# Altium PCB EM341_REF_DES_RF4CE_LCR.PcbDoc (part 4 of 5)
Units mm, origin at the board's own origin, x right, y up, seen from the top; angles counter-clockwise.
Board outline 218.38 x 83.13 mm, 2 copper layers (Top Layer, Carbon Ink Layer); 111 components, 91 nets, 369 pads, 80 vias.
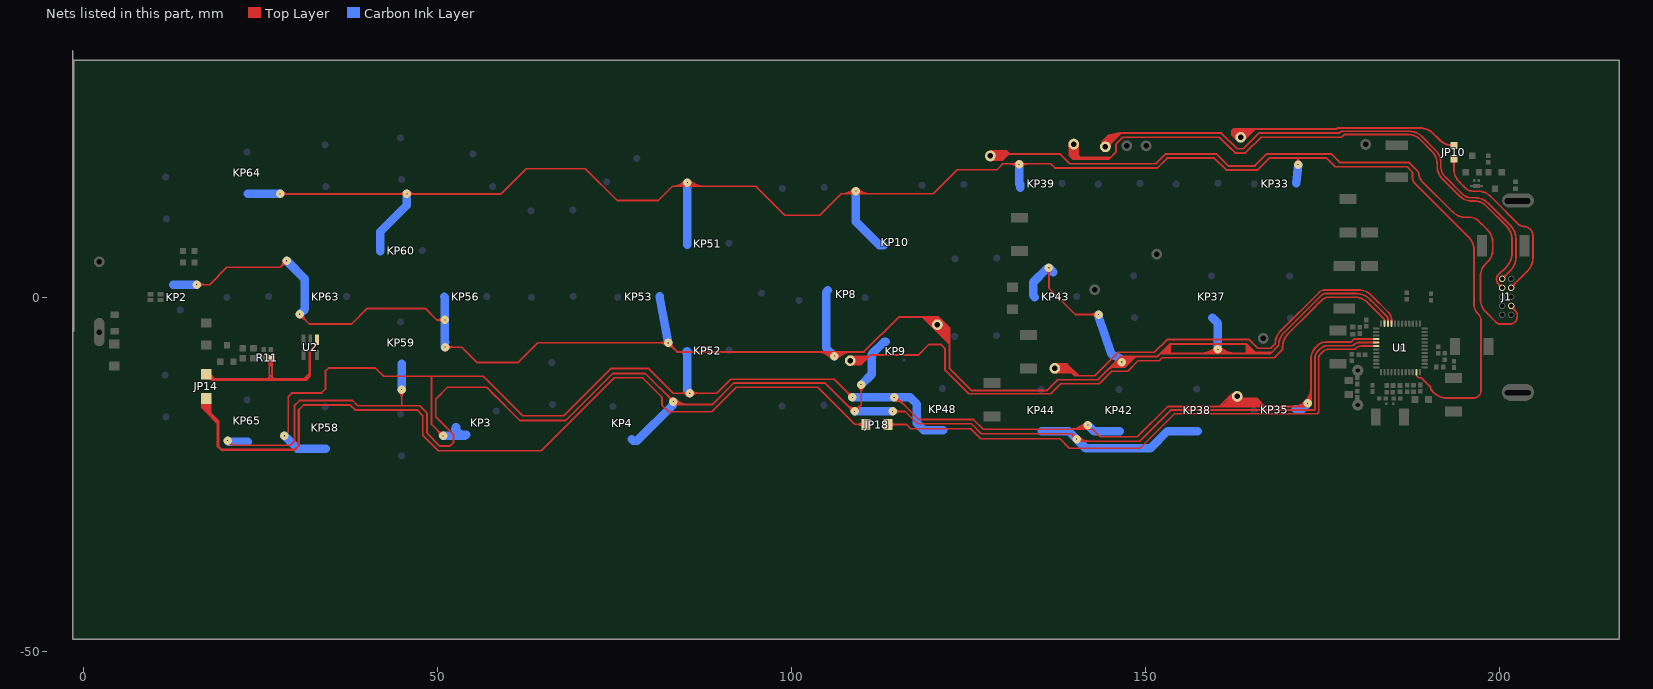
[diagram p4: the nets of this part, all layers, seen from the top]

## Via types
v1: diameter 1.2, hole 0, Top Layer to Carbon Ink Layer, 80 vias

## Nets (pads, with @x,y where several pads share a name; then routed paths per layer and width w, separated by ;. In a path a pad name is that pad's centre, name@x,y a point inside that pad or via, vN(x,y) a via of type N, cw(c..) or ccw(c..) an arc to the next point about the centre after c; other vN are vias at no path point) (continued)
PB6: JP14.2 R11.2 U2.1 | length 64
  Top Layer w0.254: JP14.2@17.31,-10.891 18.149,-11.73 ; JP14.2@17.435,-11.514 cw(c17.59,-12.289) 18.149,-11.73 ; JP14.2@17.447,-11.246 cw(c17.631,-11.722) JP14.2@17.991,-11.361 ; JP14.2@17.86,-10.891 18.699,-11.73 ; JP14.2@17.89,-11.26 18.162,-11.532 18.501,-11.532 ; JP14.2@17.924,-10.955 18.559,-11.59 31.08,-11.59 31.88,-10.79 31.88,-7.66 32.02,-7.52 ; JP14.2@17.933,-11.016 ccw(c18.708,-11.171) 18.149,-11.73 ; JP14.2@17.945,-10.891 ccw(c18.969,-10.891) 18.245,-11.615 ; 24.04,-11.59 25.96,-11.59 26.425,-11.125 ; 25.13,-11.73 31.13,-11.73 32.02,-10.84 32.02,-7.52 ; 25.82,-11.73 20.27,-11.73 18.149,-11.73 ; 26.2,-11.61 26.23,-11.58 26.23,-8.61 R11.2@26.365,-8.475 ; 26.425,-9.664 26.425,-8.475 R11.2@26.365,-8.475 ; 27.01,-11.73 26.62,-11.34 26.62,-8.825 26.365,-8.57 R11.2@26.365,-8.475 ; 30.44,-11.73 31.42,-11.73 32.02,-11.13 32.02,-10.6 ; U2.1@32.96,-5.92 32.96,-6.031 U2.1@32.954,-6.037 32.954,-6.586 32.02,-7.52 ; R11.2@26.285,-8.74 cw(c25.947,-9.078) 26.425,-9.078 ; R11.2@26.285,-8.74 cw(c25.947,-9.078) 26.425,-9.078 ; R11.2@26.285,-8.74 cw(c25.947,-9.078) 26.425,-9.078 ; R11.2@26.285,-8.74 cw(c25.947,-9.078) 26.425,-9.078 ; R11.2@26.285,-8.74 cw(c25.947,-9.078) 26.425,-9.078 ; R11.2@26.285,-8.74 cw(c25.947,-9.078) 26.425,-9.078 ; R11.2@26.285,-8.74 cw(c25.947,-9.078) 26.425,-9.078 ; R11.2@26.285,-8.74 cw(c25.947,-9.078) 26.425,-9.078 ; 26.425,-9.078 cw(c26.903,-9.078) R11.2@26.565,-8.74 ; 26.425,-9.078 cw(c26.903,-9.078) R11.2@26.565,-8.74 ; 26.425,-9.078 cw(c26.903,-9.078) R11.2@26.565,-8.74 ; 26.425,-9.078 cw(c26.903,-9.078) R11.2@26.565,-8.74 ; 26.425,-9.078 cw(c26.903,-9.078) R11.2@26.565,-8.74 ; 26.425,-9.078 cw(c26.903,-9.078) R11.2@26.565,-8.74 ; 26.425,-9.078 cw(c26.903,-9.078) R11.2@26.565,-8.74 ; 26.425,-9.078 cw(c26.903,-9.078) R11.2@26.565,-8.74 ; 32.631,-6.909 ccw(c32.21,-6.487) 32.806,-6.487 cw(c32.21,-6.487) 32.631,-6.909
PB6_1: JP14.1 JP18.2 | length 184.2
  Top Layer w0.254: 16.68,-15.453 cw(c17.439,-15.453) JP14.1@17.353,-14.699 ; 16.68,-15.168 cw(c17.407,-15.168) JP14.1@17.324,-14.446 ; 16.68,-15.11 17.493,-16.043 ; JP14.1@16.68,-14.884 cw(c17.374,-14.884) JP14.1@17.296,-14.194 ; JP14.1@16.68,-14.55 16.68,-15.59 17.429,-16.339 ; 16.92,-15.648 cw(c17.658,-15.648) JP14.1@17.471,-14.934 ; 16.92,-15.319 cw(c17.572,-15.319) JP14.1@17.407,-14.689 ; JP14.1@16.92,-14.99 cw(c17.486,-14.99) JP14.1@17.342,-14.443 ; JP14.1@16.92,-14.92 16.92,-15.59 17.16,-15.83 ; JP14.1@16.934,-14.831 cw(c16.127,-15.927) 17.488,-15.927 ; JP14.1@16.978,-14.861 cw(c16.149,-16.211) 17.733,-16.211 ; JP14.1@17.003,-14.876 cw(c16.125,-16.465) 17.94,-16.465 ; JP14.1@17.041,-14.589 cw(c16.39,-15.24) 17.31,-15.24 cw(c18.23,-15.24) JP14.1@17.579,-14.589 ; JP14.1@17.084,-14.627 cw(c16.496,-15.425) 17.488,-15.425 ; JP14.1@17.111,-14.645 cw(c16.428,-15.757) 17.733,-15.757 ; JP14.1@17.126,-14.653 cw(c16.363,-16.034) 17.94,-16.034 ; 17.16,-15.997 cw(c18.708,-15.997) JP14.1@17.717,-14.808 ; 17.16,-15.99 JP14.1@17.16,-14.57 ; 17.16,-15.491 ccw(c16.139,-15.491) 16.861,-14.769 cw(c15.777,-15.853) 17.31,-15.853 cw(c18.843,-15.853) 17.759,-14.769 ccw(c18.414,-15.424) 17.488,-15.424 ; 17.16,-15.454 cw(c18.256,-15.454) JP14.1@17.554,-14.613 ; JP14.1@17.244,-14.428 cw(c16.707,-15.303) 17.733,-15.303 ; JP14.1@17.249,-14.431 cw(c16.601,-15.603) 17.94,-15.603 ; JP14.1@17.31,-14.32 17.31,-16.22 18.9,-17.81 18.9,-21.04 19.47,-21.61 29.8,-21.61 30.42,-20.99 30.42,-15.89 ; JP14.1@17.371,-14.209 cw(c16.839,-15.173) 17.94,-15.173 ; 17.46,-16.17 19.04,-17.75 ; 17.488,-15.918 JP14.1@17.488,-14.802 ; JP14.1@17.733,-14.843 17.493,-16.043 ; JP14.1@17.94,-14.74 17.94,-16.37 19.04,-17.47 19.04,-21.07 19.58,-21.61 ; 18.92,-17.47 17.493,-16.043 ; 19.5,-21.5 29.82,-21.5 30.42,-20.9 ; 30.31,-21.01 30.31,-16 31.05,-15.26 37.66,-15.26 38.34,-15.94 47.09,-15.94 47.89,-16.74 47.89,-19.5 50.1,-21.71 64.62,-21.71 74.92,-11.41 78.93,-11.41 81.68,-14.16 81.68,-15.25 82.64,-16.21 88.7,-16.21 92.17,-12.74 103.64,-12.74 ; 103.66,-12.74 108.87,-17.95 JP18.2@110.428,-17.95 ; 109.117,-17.95 cw(c109.117,-19.383) JP18.2@110.13,-18.37 ; 109.358,-17.95 ccw(c109.358,-16.858) JP18.2@110.13,-17.63 ; 109.73,-17.95 cw(c109.73,-18.77) JP18.2@110.31,-18.19
PB6_2: JP18.1 U1.42 | length 82.9
  Top Layer w0.254: JP18.1@113.6,-18 116.22,-18 116.82,-18.6 125.28,-18.6 126.7,-20.02 137.88,-20.02 139.21,-21.35 149.18,-21.35 154.054,-16.476 174.103,-16.476 ccw(c174.103,-16.108) 174.364,-16.369 ccw(c174.239,-16.244) 174.416,-16.244 174.416,-8.618 cw(c175.208,-8.618) 174.647,-8.057 174.982,-7.723 cw(c175.8,-8.541) 175.8,-7.384 179.363,-7.384 ccw(c179.363,-7.076) 179.581,-7.294 179.698,-7.177 ; JP18.1@113.97,-18.37 cw(c114.863,-19.263) 114.863,-18 cw(c114.863,-16.737) JP18.1@113.97,-17.63 ; 179.653,-7.22 cw(c180.365,-7.932) 179.698,-7.177 ; U1.42@182.528,-6.925 180.365,-6.925 ccw(c180.365,-7.932) 179.698,-7.177
PB7: KP4.2 KP9.1 KP38.2 KP44.1 KP59.2 KP65.2 U1.41 | length 305.2
  Top Layer w0.254: v1(20.33,-20.28) 20.98,-20.93 ; 44.92,-15.33 v1(44.92,-13.07) ; 57.68,-13.51 61.6,-17.43 68.09,-17.43 74.73,-10.79 79.32,-10.79 v1@83.261,-14.731 ; 58.228,-14.058 56.92,-12.75 51.39,-12.75 49.72,-14.42 49.72,-16.9 52.25,-19.43 52.25,-20.5 51.7,-21.05 50.32,-21.05 48.51,-19.24 48.51,-16.39 47.48,-15.36 38.72,-15.36 37.97,-14.61 30.51,-14.61 29.77,-15.35 29.77,-20.36 29.2,-20.93 20.98,-20.93 ; v1@83.72,-15.19 88.78,-15.19 91.85,-12.12 104.66,-12.12 108.68,-16.14 v1(108.89,-16.14) 109.83,-15.2 109.83,-12.33 v1(109.79,-12.37) ; v1(114.25,-16.16) 116.02,-16.16 117.76,-17.9 125.38,-17.9 126.77,-19.29 139.55,-19.29 140.61,-20.35 149.14,-20.35 153.522,-15.968 173.67,-15.968 ccw(c173.67,-15.735) 173.835,-15.9 ccw(c173.687,-15.752) 173.896,-15.752 173.896,-8.553 cw(c175.061,-8.553) 174.237,-7.729 174.717,-7.249 cw(c175.618,-8.151) 175.618,-6.876 178.983,-6.876 ccw(c178.983,-6.215) 179.45,-6.683 cw(c180.072,-7.304) 180.072,-6.425 U1.41@182.528,-6.425 ; 20.98,-20.93 cw(c21.444,-20.466) 20.797,-20.358 ccw(c21.444,-20.466) 20.98,-20.93 ; 20.98,-20.93 ccw(c20.516,-21.394) 20.408,-20.747 cw(c20.516,-21.394) 20.98,-20.93 ; 44.92,-14.212 cw(c46.062,-14.212) 45.254,-13.404 ccw(c46.062,-14.212) 44.92,-14.212 ; 44.92,-14.212 ccw(c43.778,-14.212) 44.586,-13.404 cw(c43.778,-14.212) 44.92,-14.212 ; 82.493,-13.963 cw(c81.685,-14.77) 82.827,-14.77 ccw(c81.685,-14.77) 82.493,-13.963 ; 82.493,-13.963 ccw(c83.3,-13.155) 83.3,-14.297 cw(c83.3,-13.155) 82.493,-13.963 ; v1@108.89,-15.667 cw(c108.89,-14.018) 107.724,-15.184 ccw(c108.89,-14.018) v1@108.89,-15.667 ; v1@108.89,-15.667 ccw(c108.89,-14.525) 109.697,-15.333 ; v1@108.89,-15.667 ccw(c108.89,-14.525) 109.697,-15.333 ; 109.697,-15.333 ccw(c110.505,-16.14) 109.363,-16.14 cw(c110.505,-16.14) 109.697,-15.333 ; 115.392,-16.16 cw(c115.392,-15.018) 114.584,-15.826 ccw(c115.392,-15.018) 115.392,-16.16 ; 115.392,-16.16 ccw(c115.392,-17.302) 114.584,-16.494 cw(c115.392,-17.302) 115.392,-16.16 ; v1@83.275,-14.795 ccw(c84.229,-13.841) 84.229,-15.19 cw(c84.229,-13.841) v1@83.275,-14.795 ; v1@83.455,-14.615 ccw(c84.843,-13.227) 84.843,-15.19 cw(c84.843,-13.227) v1@83.455,-14.615 ; v1@83.634,-14.436 ccw(c85.456,-12.614) 85.456,-15.19 cw(c85.456,-12.614) v1@83.634,-14.436 ; 108.158,-15.618 ccw(c108.89,-14.885) 108.89,-15.921 cw(c108.89,-14.885) 108.158,-15.618 ; 108.231,-15.691 cw(c107.782,-16.14) 108.417,-16.14 ccw(c107.782,-16.14) 108.231,-15.691 ; v1@109.456,-12.704 cw(c108.552,-13.608) 109.83,-13.608 ccw(c108.552,-13.608) v1@109.456,-12.704 ; v1@109.635,-12.525 cw(c109.165,-12.995) 109.83,-12.995 ccw(c109.165,-12.995) v1@109.635,-12.525 ; 109.83,-13.415 cw(c110.835,-13.415) 110.124,-12.704 ccw(c110.835,-13.415) 109.83,-13.415 ; 139.505,-19.245 cw(c138.869,-19.881) 139.761,-19.998 ccw(c138.869,-19.881) 139.505,-19.245 ; 139.576,-19.316 ccw(c140.23,-18.662) 140.23,-19.587 cw(c140.23,-18.662) 139.576,-19.316 ; v1@140.205,-20.085 ccw(c140.846,-19.444) 140.846,-20.35 cw(c140.846,-19.444) v1@140.205,-20.085 ; v1@140.385,-19.905 ccw(c141.459,-18.831) 141.459,-20.35 cw(c141.459,-18.831) v1@140.385,-19.905 ; v1@140.564,-19.726 ccw(c142.072,-18.218) 142.072,-20.35 cw(c142.072,-18.218) v1@140.564,-19.726
  Carbon Ink Layer w1.2: v1(20.33,-20.28) 20.467,-20.417 KP65.2@23.21,-20.417 ; v1@44.91,-13.05 KP59.2@44.91,-9.44 ; KP4.2@77.434,-20.114 77.59,-20.27 78.18,-20.27 83.3,-15.15 v1(83.3,-14.77) ; v1@108.89,-16.15 v1@114.25,-16.14 ; v1(109.79,-12.37) 109.79,-12.41 111.3,-10.9 111.3,-8.06 113.08,-6.28 KP9.1@113.309,-6.28 ; KP44.1@135.33,-18.966 139.136,-18.966 141.52,-21.35 150.65,-21.35 153.083,-18.917 KP38.2@157.31,-18.917 ; v1(83.3,-14.77) cw(c82.383,-14.77) 83.031,-15.419 ccw(c82.383,-14.77) v1(83.3,-14.77)
  other v1: 140.23,-20.06
PC0: 
PC0_1: 
PC0_2: KP3.1 KP35.2 KP42.1 KP48.2 KP52.2 KP58.2 pad.8 U1.40 | length 322.5
  Top Layer w0.254: v1(28.36,-19.58) 28.9,-19.04 28.9,-14.08 29.45,-13.53 33.6,-13.53 34.14,-12.99 34.14,-10.48 34.6,-10.02 41.2,-10.02 42.37,-11.19 56.44,-11.19 62.02,-16.77 67.8,-16.77 74.47,-10.1 79.81,-10.1 83.29,-13.58 89.41,-13.58 91.39,-11.6 106,-11.6 v1(108.57,-14.17) ; 49.13,-11.23 49.13,-17.99 v1(50.76,-19.62) ; v1@114.84,-14.55 114.85,-14.18 117.96,-17.29 125.66,-17.29 127.03,-18.66 142.49,-18.66 143.57,-19.74 148.81,-19.74 153.09,-15.46 172.997,-15.46 ccw(c172.997,-15.134) 173.227,-15.365 ccw(c172.986,-15.124) 173.327,-15.124 173.327,-8.787 cw(c175.867,-8.787) 174.071,-6.991 174.196,-6.866 cw(c175.399,-8.069) 175.399,-6.368 178.853,-6.368 ccw(c178.853,-6.05) 179.077,-6.275 179.442,-5.91 182.513,-5.91 U1.40@182.528,-5.925 ; 160.399,-15.46 162.148,-13.712 ; 160.606,-15.254 160.936,-15.254 pad.8@162.208,-13.982 ; 161.06,-15.46 pad.8@162.428,-14.092 ; 161.412,-15.368 pad.8@162.628,-14.152 ; 161.672,-15.358 pad.8@162.888,-14.142 ; 161.832,-15.398 pad.8@163.048,-14.182 ; 162.032,-15.408 pad.8@163.248,-14.192 ; 162.27,-15.361 pad.8@162.27,-13.64 ; pad.8@162.451,-14.279 cw(c161.367,-15.363) 162.9,-15.363 cw(c164.433,-15.363) pad.8@163.349,-14.279 ; 162.47,-15.45 pad.8@162.47,-13.73 ; 162.59,-15.45 pad.8@162.59,-13.73 ; pad.8@162.631,-14.099 cw(c161.98,-14.75) 162.9,-14.75 cw(c163.82,-14.75) pad.8@163.169,-14.099 ; 162.81,-15.46 pad.8@162.81,-13.74 ; 162.9,-15.46 pad.8@162.9,-13.74 ; 163.1,-15.46 pad.8@163.1,-13.74 ; 163.24,-15.46 pad.8@163.24,-13.74 ; 163.349,-15.38 pad.8@163.349,-13.659 ; 163.55,-15.44 pad.8@163.55,-13.72 ; 163.59,-14.76 165.65,-14.76 166.23,-15.34 ; 163.63,-14.95 165.66,-14.95 166.06,-15.35 ; 163.64,-14.52 165.63,-14.52 166.46,-15.35 ; 163.689,-14.3 165.66,-14.3 166.67,-15.31 ; 163.709,-15.2 165.76,-15.2 165.9,-15.34 ; 170.679,-15.46 ccw(c170.679,-12.849) 172.526,-14.696 ccw(c170.589,-12.759) 173.327,-12.759 ; 171.292,-15.46 ccw(c171.292,-13.462) 172.705,-14.875 ccw(c171.203,-13.373) 173.327,-13.373 ; 171.905,-15.46 ccw(c171.905,-14.075) 172.885,-15.055 ccw(c171.816,-13.986) 173.327,-13.986 ; v1@173.064,-15.234 ccw(c172.429,-14.599) 173.327,-14.599 ; v1@173.18,-15.28 v1@173.24,-15.22 ; 49.953,-18.813 cw(c49.145,-19.62) 50.287,-19.62 ccw(c49.145,-19.62) 49.953,-18.813 ; 49.953,-18.813 ccw(c50.76,-18.005) 50.76,-19.147 cw(c50.76,-18.005) 49.953,-18.813 ; 84.458,-13.58 cw(c84.458,-14.722) 85.266,-13.914 ccw(c84.458,-14.722) 84.458,-13.58 ; 84.458,-13.58 ccw(c84.458,-12.438) 85.266,-13.246 cw(c84.458,-12.438) 84.458,-13.58 ; 86.742,-13.58 cw(c86.742,-12.438) 85.934,-13.246 ccw(c86.742,-12.438) 86.742,-13.58 ; 86.742,-13.58 ccw(c86.742,-14.722) 85.934,-13.914 cw(c86.742,-14.722) 86.742,-13.58 ; 107.763,-13.363 cw(c106.955,-14.17) 108.097,-14.17 ccw(c106.955,-14.17) 107.763,-13.363 ; 107.763,-13.363 ccw(c108.57,-12.555) 108.57,-13.697 cw(c108.57,-12.555) 107.763,-13.363 ; v1@114.47,-14.643 cw(c114.47,-16.678) 115.909,-15.239 ccw(c114.47,-16.678) v1@114.47,-14.643 ; v1@114.47,-14.389 cw(c114.47,-15.811) 115.475,-14.805 ccw(c114.47,-15.811) v1@114.47,-14.389 ; v1@114.47,-14.135 cw(c114.47,-14.944) 115.042,-14.372 ccw(c114.47,-14.944) v1@114.47,-14.135 ; 139.268,-18.66 ccw(c139.268,-15.538) 141.476,-17.746 cw(c139.268,-15.538) 139.268,-18.66 ; 139.881,-18.66 ccw(c139.881,-16.151) 141.655,-17.925 cw(c139.881,-16.151) 139.881,-18.66 ; 140.494,-18.66 ccw(c140.494,-16.764) 141.835,-18.105 cw(c140.494,-16.764) 140.494,-18.66 ; 141.107,-18.66 ccw(c141.107,-17.377) 142.014,-18.284 cw(c141.107,-17.377) 141.107,-18.66
  Carbon Ink Layer w1.2: v1(28.36,-19.58) 30.187,-21.407 KP58.2@34.21,-21.407 ; v1@50.77,-19.61 51.05,-19.61 51.06,-19.62 53.83,-19.62 KP3.1@53.93,-19.52 ; 52.48,-18.69 53.227,-19.437 KP3.1@54.04,-19.437 ; 52.56,-18.38 52.61,-18.38 ; KP52.2@85.08,-7.773 KP52.2@85.223,-7.63 85.223,-13.203 v1(85.6,-13.58) ; v1(108.57,-14.17) v1@114.46,-14.17 ; v1(114.47,-14.17) 116.73,-14.17 117.68,-15.12 117.68,-17.83 118.667,-18.817 KP48.2@121.4,-18.817 ; v1(141.81,-18.08) 142.686,-18.956 KP42.1@146.33,-18.956 ; KP35.2@171.187,-15.86 172.03,-15.86 v1(172.86,-15.03) ; v1(85.6,-13.58) cw(c86.51,-12.67) 85.223,-12.67 ccw(c86.51,-12.67) v1(85.6,-13.58)
PC0_3: JP10.1 pad.0@163.4,22.55 | length 61.3
  Top Layer w0.254: 162.174,23.126 pad.0@162.945,22.355 ; 162.244,23.276 pad.0@163.015,22.505 ; 162.244,23.416 pad.0@163.015,22.645 ; 162.324,23.526 pad.0@163.095,22.755 ; 162.504,23.566 pad.0@163.275,22.795 ; 162.61,22.81 cw(c163.19,22.72) pad.0@163.28,23.3 ; 162.644,23.606 pad.0@163.415,22.835 ; pad.0@162.82,22.22 162.15,22.89 162.15,23.48 162.41,23.74 176.95,23.74 177.075,23.865 188.74,23.865 ; 162.834,23.606 pad.0@163.605,22.835 ; 162.994,23.636 pad.0@163.765,22.865 ; 163.102,23.395 164.192,23.395 ; 163.113,23.267 cw(c163.459,22.793) 163.933,23.14 ; 163.114,23.646 pad.0@163.885,22.875 ; 163.177,23.54 164.267,23.54 ; 163.274,23.656 pad.0@164.045,22.885 ; pad.0@163.4,22.931 ccw(c163.4,23.73) 163.965,23.165 ; pad.0@163.4,23.185 ccw(c163.4,24.597) 164.399,23.599 ; pad.0@163.48,22.68 164.54,23.74 ; 163.66,23.28 cw(c163.57,22.7) pad.0@164.15,22.61 ; pad.0@163.71,22.29 164,22.29 165.395,23.685 ; pad.0@163.781,22.55 cw(c164.822,22.55) 164.086,23.286 ; pad.0@164.035,22.55 cw(c165.689,22.55) 164.519,23.719 ; pad.0@164.054,22.904 164.825,23.675 ; 164.234,22.914 165.005,23.685 ; 164.254,22.784 165.025,23.555
  Top Layer w0.292: 188.74,23.865 cw(c188.74,21.325) 190.536,23.121 191.484,22.174 ccw(c193.28,23.97) 193.28,21.43 JP10.1@193.514,21.43 ; JP10.1@193.195,21.775 cw(c193.195,21.34) 193.503,21.648 cw(c193.394,21.539) 193.547,21.539 JP10.1@193.547,21.32
PC0_4: J1.3 JP10.2 | length 31.9
  Top Layer w0.254: JP10.2@193.514,19.53 193.514,18.057 ccw(c196.054,18.057) 194.258,16.261 194.795,15.724 194.799,15.724 195.127,15.396 ccw(c196.218,16.488) 196.218,14.944 196.911,14.944 cw(c196.911,12.404) 198.518,14.371 cw(c196.911,12.404) 198.707,14.2 198.99,13.918 ; 198.986,13.914 202.606,10.294 ccw(c203.382,11.071) 203.382,9.972 cw(c203.382,8.771) 204.232,9.621 204.321,9.532 cw(c203.501,8.712) 204.66,8.712 204.66,5.5 cw(c202.12,5.5) 203.916,3.704 J1.3@201.595,1.382 ; 193.514,18.63 cw(c194.415,18.63) 193.778,19.266 ccw(c194.415,18.63) 193.514,18.63 ; 193.514,18.63 ccw(c192.614,18.63) 193.25,19.266 cw(c192.614,18.63) 193.514,18.63 ; J1.3@201.585,1.618 ccw(c201.585,2.211) 202.004,1.792 ; J1.3@201.585,1.618 ccw(c201.585,2.211) 202.004,1.792 ; J1.3@201.585,1.618 ccw(c201.585,2.211) 202.004,1.792 ; J1.3@201.908,1.295 cw(c202.875,1.295) 202.191,1.979 ; J1.3@201.908,1.295 cw(c202.875,1.295) 202.191,1.979 ; J1.3@201.908,1.295 cw(c202.875,1.295) 202.191,1.979
PC0_5: 
PC2: pad.1@137.15,-10.07 U1.33 | length 82
  Top Layer w0.254: pad.1@136.59,-10.3 139.57,-10.3 ; pad.1@136.64,-9.73 138.837,-9.73 ; pad.1@136.66,-10.07 138.12,-10.07 ; pad.1@136.73,-10.15 138.19,-10.15 ; pad.1@136.74,-10.5 139.67,-10.5 ; pad.1@136.74,-9.96 139.22,-9.96 ; pad.1@136.85,-9.53 137.98,-9.53 ; pad.1@136.96,-10.67 139.84,-10.67 140.27,-11.1 ; pad.1@136.99,-9.45 138.87,-9.45 140.52,-11.1 ; pad.1@137.44,-9.55 138.9,-9.55 ; pad.1@137.64,-9.84 139.1,-9.84 ; 137.92,-10.1 139.38,-10.1 ; 138.855,-10.01 139.945,-11.1 142.78,-11.1 146.08,-7.8 151.22,-7.8 153.01,-6.01 164.59,-6.01 165.81,-7.23 167.651,-7.23 168.265,-6.616 cw(c170.805,-6.616) 169.009,-4.82 174.537,0.708 cw(c175.268,-0.023) 175.268,1.01 ; 138.967,-9.57 138.978,-9.558 ; 175.291,0.999 180.038,0.999 cw(c180.038,-1.541) 181.834,0.255 184.266,-2.176 ; 184.245,-2.152 cw(c183.138,-3.259) 184.703,-3.259 U1.33@184.703,-3.75
PC2_1: 
PC2_2: 
PC2_3: J1.2 pad.2@144.3,21.22 | length 135.8
  Top Layer w0.254: pad.2@143.9,21.28 143.9,22.02 144.68,22.8 146.27,23.16 ; pad.2@144.003,21.857 cw(c144.349,21.383) pad.2@144.823,21.73 ; pad.2@144.16,21.26 144.16,22.06 144.71,22.61 145.48,22.61 ; pad.2@144.19,21.08 146.27,23.16 ; pad.2@144.3,21.4 145.7,22.8 ; pad.2@144.32,21.69 144.32,21.92 144.96,22.56 ; pad.2@144.6,21.27 146.49,23.16 ; 145.91,22.95 144.96,22.61 144.96,22.56 ; 188.955,22.684 190.904,20.736 cw(c189.108,18.939) 191.648,18.939 191.648,18.555 ccw(c193.983,18.555) 192.332,16.903 194.655,14.58 ccw(c196.026,15.951) 196.026,14.012 196.568,14.012 cw(c196.568,11.608) 198.268,13.308 201.521,10.054 cw(c199.725,8.258) 202.265,8.258 202.265,5.567 cw(c199.725,5.567) 201.521,3.771 J1.2@200.315,2.565 ; 188.962,22.691 ccw(c187.245,20.974) 187.245,23.402 177.582,23.402 177.34,23.16 165.97,23.16 163.74,20.93 162.91,20.93 160.68,23.16 146.27,23.16 ; pad.2@144.3,21.601 ccw(c144.3,23.124) 145.377,22.047 cw(c144.3,23.124) pad.2@144.3,21.601 ; pad.2@144.3,21.601 ccw(c144.3,22.593) 145.002,21.892 cw(c144.3,22.593) pad.2@144.3,21.601 ; pad.2@144.3,21.855 ccw(c144.3,22.326) 144.633,21.993 cw(c144.3,22.326) pad.2@144.3,21.855 ; pad.2@144.3,21.855 ccw(c144.3,23.992) 145.811,22.481 cw(c144.3,23.992) pad.2@144.3,21.855 ; pad.2@144.3,21.855 ccw(c144.3,23.46) 145.435,22.325 cw(c144.3,23.46) pad.2@144.3,21.855 ; pad.2@144.3,21.855 ccw(c144.3,22.881) 145.026,22.156 cw(c144.3,22.881) pad.2@144.3,21.855 ; pad.2@144.3,21.855 ccw(c144.3,22.953) 145.077,22.177 cw(c144.3,22.953) pad.2@144.3,21.855 ; pad.2@144.681,21.22 cw(c145.528,21.22) 144.929,21.819 ccw(c145.528,21.22) pad.2@144.681,21.22 ; pad.2@144.681,21.22 cw(c146.035,21.22) 145.078,22.178 ccw(c146.035,21.22) pad.2@144.681,21.22 ; pad.2@144.935,21.22 cw(c145.864,21.22) 145.207,21.877 ccw(c145.864,21.22) pad.2@144.935,21.22 ; pad.2@144.935,21.22 cw(c146.396,21.22) 145.363,22.253 ccw(c146.396,21.22) pad.2@144.935,21.22 ; pad.2@144.935,21.22 cw(c146.903,21.22) 145.511,22.611 ccw(c146.903,21.22) pad.2@144.935,21.22 ; 144.96,22.56 ccw(c145.539,21.981) 144.841,21.552 cw(c145.539,21.981) 144.96,22.56 ; 145.15,22.51 ccw(c145.891,21.769) 144.9,21.427 cw(c145.891,21.769) 145.15,22.51 ; 145.15,22.51 144.49,21.85 144.49,21.62 145.48,22.61 ; 145.48,22.61 ccw(c146.798,21.292) 144.935,21.238 cw(c146.798,21.292) 145.48,22.61 ; J1.2@200.315,2.888 ccw(c200.315,3.668) 200.866,3.116 ; J1.2@200.315,2.888 ccw(c200.315,3.668) 200.866,3.116 ; J1.2@200.315,2.888 ccw(c200.315,3.668) 200.866,3.116 ; J1.2@200.638,2.565 cw(c201.418,2.565) 200.866,3.116 ; J1.2@200.638,2.565 cw(c201.418,2.565) 200.866,3.116 ; J1.2@200.638,2.565 cw(c201.418,2.565) 200.866,3.116 ; pad.2@144.408,21.286 cw(c144.975,21.634) 144.505,22.105 ccw(c144.975,21.634) pad.2@144.408,21.286 ; pad.2@144.42,21.261 cw(c145.037,21.474) 144.575,21.935 ccw(c145.037,21.474) pad.2@144.42,21.261 ; pad.2@144.625,21.419 cw(c145.257,21.808) 144.732,22.332 ccw(c145.257,21.808) pad.2@144.625,21.419 ; pad.2@144.66,21.344 cw(c145.464,21.622) 144.863,22.223 ccw(c145.464,21.622) pad.2@144.66,21.344 ; pad.2@144.681,21.231 cw(c145.988,21.269) 145.063,22.193 ccw(c145.988,21.269) pad.2@144.681,21.231
PC3: KP2.2 KP8.1 KP37.2 KP43.2 KP53.1 KP56.2 KP63.2 pad.0@120.57,-3.91 U1.34 | length 642.3
  Top Layer w0.254: v1@15.98,1.75 17.79,1.75 20.24,4.2 27.74,4.2 v1@28.695,5.155 ; v1@16.294,1.436 cw(c17.054,0.676) 17.054,1.75 ; v1@16.294,2.104 ccw(c17.15,2.96) 17.15,1.75 ; v1@28.197,5.13 cw(c27.055,5.13) 27.863,4.323 cw(c28.67,3.515) v1@28.67,4.657 ; v1(30.51,-2.43) 31.88,-3.8 37.88,-3.8 40.07,-1.61 48.25,-1.61 49.879,-3.239 v1(51.029,-3.239) ; v1@51,-7.08 53.4,-7.08 55.58,-9.26 61.3,-9.26 63.48,-7.08 ; v1@51.374,-7.414 cw(c52.182,-8.222) 52.182,-7.08 cw(c52.182,-5.938) v1@51.374,-6.746 ; 62.419,-8.141 64.12,-6.44 82.5,-6.44 83.81,-7.75 110.19,-7.75 115.11,-2.83 120.73,-2.83 122.26,-4.36 122.26,-10.05 125.418,-13.208 136.032,-13.208 137.56,-11.68 143.19,-11.68 146.46,-8.41 151.63,-8.41 153.43,-6.61 ; 81.322,-6.44 cw(c81.322,-7.718) v1@82.226,-6.814 ; 81.515,-6.44 ccw(c81.515,-5.435) v1@82.226,-6.146 ; 81.935,-6.44 cw(c81.935,-7.105) v1@82.405,-6.635 ; v1@82.56,-6.953 cw(c82.56,-8.047) 83.333,-7.273 ; v1@83.033,-6.48 ccw(c84.223,-6.48) 83.382,-7.322 ; 104.81,-7.75 104.83,-7.77 v1(106.02,-8.35) ; 118.47,-2.83 122.26,-6.62 ; 118.76,-2.83 122.26,-6.33 ; 119.43,-3.01 121.99,-5.57 ; pad.0@119.937,-3.859 119.988,-3.228 122.26,-5.5 ; 120.1,-3.01 122.1,-5.01 ; 120.49,-2.83 122.1,-4.44 122.1,-5.96 119.15,-3.01 120.44,-3.01 122.05,-4.62 ; pad.0@120.613,-4.03 cw(c121.16,-5.564) 122.312,-4.412 ; v1@135.976,3.806 cw(c135.168,2.998) 136.31,2.998 cw(c137.452,2.998) v1@136.644,3.806 ; v1@136.023,3.77 cw(c135.521,3.148) 136.32,3.148 cw(c137.119,3.148) v1@136.617,3.77 ; v1(136.31,4.14) 136.31,1.28 140.07,-2.48 v1(143.33,-2.48) ; v1@142.922,-2.777 ccw(c142.3,-3.279) 142.3,-2.48 ccw(c142.3,-1.681) v1@142.922,-2.183 ; v1@142.996,-2.814 ccw(c142.188,-3.622) 142.188,-2.48 ccw(c142.188,-1.338) v1@142.996,-2.146 ; 147.31,-8.86 146.8,-9.37 145.96,-9.37 ; 147.87,-8.52 147.87,-8.61 ; 148.5,-8.41 147,-9.91 144.96,-9.91 ; 152.07,-7.97 167.63,-7.97 168.772,-6.827 cw(c171.312,-6.827) 169.516,-5.031 173.471,-1.077 ; 152.37,-7.84 152.42,-7.84 153.08,-7.18 153.08,-7.75 152.72,-7.75 152.65,-7.82 152.77,-7.82 153.08,-7.51 ; 153.217,-7.753 153.217,-6.823 ; 153.43,-7.9 153.43,-6.61 ; v1(160.19,-7.4) 160.19,-6.62 ; 164.38,-6.92 165.27,-7.81 164.37,-7.81 164.22,-7.96 164.22,-6.61 ; 164.4,-6.94 164.4,-7.62 164.424,-7.596 165.056,-7.596 ; 164.69,-7.23 164.53,-7.23 164.57,-7.27 164.57,-7.596 164.71,-7.456 ; 167.81,-7.79 165.4,-7.79 164.22,-6.61 ; 173.47,-1.085 174.806,0.251 cw(c175.386,-0.33) 175.386,0.491 179.784,0.491 cw(c179.784,-2.049) 181.58,-0.253 182.437,-1.11 ; 182.436,-1.111 184.008,-2.682 ; 184.028,-2.682 cw(c183.603,-3.107) 184.203,-3.107 U1.34@184.203,-3.75 ; 31.317,-3.237 cw(c32.125,-2.43) 30.983,-2.43 ccw(c32.125,-2.43) 31.317,-3.237 ; 31.317,-3.237 ccw(c30.51,-4.045) 30.51,-2.903 cw(c30.51,-4.045) 31.317,-3.237 ; 49.887,-3.239 cw(c49.887,-4.381) 50.694,-3.573 ccw(c49.887,-4.381) 49.887,-3.239 ; 49.887,-3.239 ccw(c49.887,-2.097) 50.694,-2.904 cw(c49.887,-2.097) 49.887,-3.239 ; 104.994,-7.85 cw(c104.493,-8.876) 105.573,-8.504 ccw(c104.493,-8.876) 104.994,-7.85 ; 104.994,-7.85 ccw(c105.494,-6.823) 105.866,-7.903 cw(c105.494,-6.823) 104.994,-7.85 ; pad.0@120.357,-3.312 cw(c120.712,-4.308) 121.46,-3.56 ccw(c120.712,-4.308) pad.0@120.357,-3.312 ; pad.0@120.357,-3.312 cw(c120.097,-2.583) 119.55,-3.13 ccw(c120.097,-2.583) pad.0@120.357,-3.312 ; pad.0@120.442,-3.551 cw(c120.861,-4.727) 121.744,-3.844 ccw(c120.861,-4.727) pad.0@120.442,-3.551 ; pad.0@120.442,-3.551 cw(c120.246,-3.002) 119.834,-3.414 ccw(c120.246,-3.002) pad.0@120.442,-3.551 ; pad.0@120.57,-4.545 cw(c120.57,-6.319) 121.825,-5.065 ccw(c120.57,-6.319) pad.0@120.57,-4.545 ; pad.0@120.57,-4.545 cw(c120.57,-5.499) 121.244,-4.824 ccw(c120.57,-5.499) pad.0@120.57,-4.545 ; pad.0@120.57,-3.275 cw(c120.57,-1.983) 119.657,-2.897 ccw(c120.57,-1.983) pad.0@120.57,-3.275 ; pad.0@120.57,-3.275 cw(c120.57,-2.78) 120.22,-3.13 ccw(c120.57,-2.78) pad.0@120.57,-3.275 ; pad.0@121.205,-3.91 ccw(c122.497,-3.91) 121.583,-4.823 cw(c122.497,-3.91) pad.0@121.205,-3.91 ; pad.0@121.205,-3.91 ccw(c121.7,-3.91) 121.35,-4.26 cw(c121.7,-3.91) pad.0@121.205,-3.91 ; pad.0@121.205,-3.91 ccw(c123.317,-3.91) 121.824,-5.404 cw(c123.317,-3.91) pad.0@121.205,-3.91 ; 144.96,-9.91 ccw(c144.96,-8.659) 146.15,-9.044 cw(c144.96,-8.659) 144.96,-9.91 ; 145.36,-9.77 ccw(c145.36,-8.986) 146.133,-9.113 cw(c145.36,-8.986) 145.36,-9.77 ; 145.36,-9.77 146.93,-9.77 148.29,-8.41 ; 145.36,-9.77 146.61,-8.52 148.07,-8.52 ; 145.605,-9.53 ccw(c145.605,-8.987) 146.137,-9.096 cw(c145.605,-8.987) 145.605,-9.53 ; 145.605,-9.53 146.95,-9.53 147.87,-8.61 ; 145.605,-9.53 146.505,-8.63 147.65,-8.63 147.42,-8.86 ; 145.96,-9.37 cw(c145.96,-9.742) 146.242,-9.499 ccw(c145.96,-9.742) 145.96,-9.37 ; 145.96,-9.37 146.47,-8.86 147.42,-8.86 ; 147.42,-8.86 ccw(c147.42,-9.207) 147.073,-9.2 cw(c147.42,-9.207) 147.42,-8.86 ; 147.87,-8.61 cw(c147.235,-7.975) 146.819,-8.771 ccw(c147.235,-7.975) 147.87,-8.61 ; 148.07,-8.52 ccw(c148.07,-9.564) 147.058,-9.307 cw(c148.07,-9.564) 148.07,-8.52 ; 148.29,-8.41 cw(c147.264,-7.384) 146.763,-8.746 ccw(c147.264,-7.384) 148.29,-8.41 ; 153.43,-6.61 164.22,-6.61 ; 160.19,-6.62 cw(c159.783,-6.62) 159.971,-6.981 ccw(c159.783,-6.62) 160.19,-6.62 ; 160.19,-6.62 ccw(c160.597,-6.62) 160.409,-6.981 cw(c160.597,-6.62) 160.19,-6.62 ; 103.43,-7.75 cw(c103.43,-10.94) 105.686,-8.684 ccw(c103.43,-10.94) 103.43,-7.75 ; 104.043,-7.75 cw(c104.043,-10.327) 105.865,-8.505 ccw(c104.043,-10.327) 104.043,-7.75 ; 104.656,-7.75 cw(c104.656,-9.714) 106.045,-8.325 ccw(c104.656,-9.714) 104.656,-7.75 ; 105.269,-7.75 cw(c105.269,-9.101) 106.224,-8.146 ccw(c105.269,-9.101) 105.269,-7.75 ; 105.456,-7.786 cw(c105.544,-7.874) 105.544,-7.75 ccw(c105.544,-7.874) 105.456,-7.786 ; v1@105.636,-7.966 cw(c106.158,-8.488) 106.158,-7.75 ccw(c106.158,-8.488) v1@105.636,-7.966 ; v1@105.816,-8.146 cw(c106.771,-9.101) 106.771,-7.75 ccw(c106.771,-9.101) v1@105.816,-8.146 ; 105.882,-7.75 cw(c105.882,-8.488) 106.404,-7.966 ccw(c105.882,-8.488) 105.882,-7.75 ; v1@105.995,-8.325 cw(c107.384,-9.714) 107.384,-7.75 ccw(c107.384,-9.714) v1@105.995,-8.325 ; v1@106.175,-8.505 cw(c107.997,-10.327) 107.997,-7.75 ccw(c107.997,-10.327) v1@106.175,-8.505 ; v1@106.354,-8.684 cw(c108.61,-10.94) 108.61,-7.75 ccw(c108.61,-10.94) v1@106.354,-8.684 ; 106.496,-7.75 cw(c106.496,-7.874) 106.584,-7.786 ccw(c106.496,-7.874) 106.496,-7.75 ; 118.98,-3.34 ccw(c119.619,-2.701) 120.177,-3.411 cw(c119.619,-2.701) 118.98,-3.34 ; 119.125,-3.195 ccw(c119.799,-2.521) 120.262,-3.355 cw(c119.799,-2.521) 119.125,-3.195 ; 119.182,-3.542 ccw(c119.797,-2.928) 120.334,-3.611 cw(c119.797,-2.928) 119.182,-3.542 ; 119.363,-3.433 ccw(c119.969,-2.827) 120.385,-3.577 cw(c119.969,-2.827) 119.363,-3.433 ; 119.385,-3.745 ccw(c119.975,-3.154) 120.491,-3.81 cw(c119.975,-3.154) 119.385,-3.745 ; 119.41,-3.27 ccw(c119.887,-2.793) 120.239,-3.368 cw(c119.887,-2.793) 119.41,-3.27 ; 119.587,-3.947 ccw(c120.153,-3.38) 120.649,-4.01 cw(c120.153,-3.38) 119.587,-3.947 ; 119.602,-3.672 ccw(c120.139,-3.134) 120.508,-3.799 cw(c120.139,-3.134) 119.602,-3.672 ; 119.638,-3.498 ccw(c120.06,-3.076) 120.371,-3.585 cw(c120.06,-3.076) 119.638,-3.498 ; 119.656,-3.236 cw(c118.981,-3.91) 119.935,-3.91 ccw(c118.981,-3.91) 119.656,-3.236 ; 119.789,-4.149 ccw(c120.331,-3.607) 120.806,-4.209 cw(c120.331,-3.607) 119.789,-4.149 ; 119.929,-3.169 cw(c119.29,-3.807) 120.19,-3.879 ccw(c119.29,-3.807) 119.929,-3.169 ; 120.128,-3.038 cw(c119.711,-3.456) 120.233,-3.732 ccw(c119.711,-3.456) 120.128,-3.038 ; pad.0@120.201,-3.817 ccw(c121.247,-4.081) 120.484,-4.844 cw(c121.247,-4.081) pad.0@120.201,-3.817 ; 120.271,-3.073 cw(c120.563,-3.89) 121.176,-3.276 ccw(c120.563,-3.89) 120.271,-3.073 ; 120.443,-3.013 cw(c120.019,-3.437) 120.474,-3.827 ccw(c120.019,-3.437) 120.443,-3.013 ; pad.0@120.444,-3.896 ccw(c121.597,-4.026) 120.776,-4.846 cw(c121.597,-4.026) pad.0@120.444,-3.896 ; pad.0@120.447,-3.879 ccw(c121.753,-4.208) 120.8,-5.16 cw(c121.753,-4.208) pad.0@120.447,-3.879 ; pad.0@120.448,-3.549 cw(c120.757,-4.466) 121.442,-3.782 ccw(c120.757,-4.466) pad.0@120.448,-3.549 ; pad.0@120.527,-3.79 cw(c121.011,-5.146) 122.028,-4.128 ccw(c121.011,-5.146) pad.0@120.527,-3.79 ; pad.0@120.529,-3.79 cw(c120.903,-4.899) 121.731,-4.071 ccw(c120.903,-4.899) pad.0@120.529,-3.79 ; pad.0@120.54,-3.787 cw(c120.777,-4.751) 121.479,-4.049 ccw(c120.777,-4.751) pad.0@120.54,-3.787 ; pad.0@120.57,-4.291 cw(c120.57,-5.452) 121.391,-4.631 ccw(c120.57,-5.452) pad.0@120.57,-4.291 ; pad.0@120.574,-4.037 cw(c120.616,-5.269) 121.487,-4.397 ccw(c120.616,-5.269) pad.0@120.574,-4.037 ; pad.0@120.583,-4.291 cw(c120.643,-6.07) 121.901,-4.811 ccw(c120.643,-6.07) pad.0@120.583,-4.291 ; pad.0@120.6,-4.033 cw(c120.902,-5.263) 121.798,-4.368 ccw(c120.902,-5.263) pad.0@120.6,-4.033 ; 120.603,-2.943 cw(c120.043,-3.504) 120.671,-3.988 ccw(c120.043,-3.504) 120.603,-2.943 ; pad.0@120.611,-4.03 cw(c121.049,-5.332) 122.021,-4.361 ccw(c121.049,-5.332) pad.0@120.611,-4.03 ; pad.0@120.661,-4.28 cw(c121.028,-5.774) 122.116,-4.686 ccw(c121.028,-5.774) pad.0@120.661,-4.28 ; pad.0@120.693,-3.941 ccw(c122.258,-4.336) 121.117,-5.477 cw(c122.258,-4.336) pad.0@120.693,-3.941 ; pad.0@120.696,-3.924 ccw(c122.267,-4.102) 121.149,-5.219 cw(c122.267,-4.102) pad.0@120.696,-3.924 ; pad.0@120.697,-3.92 ccw(c121.964,-4.025) 121.065,-4.925 cw(c121.964,-4.025) pad.0@120.697,-3.92 ; 120.808,-3.148 cw(c120.274,-3.682) 120.872,-4.143 ccw(c120.274,-3.682) 120.808,-3.148 ; pad.0@120.939,-4.003 ccw(c122.764,-4.463) 121.433,-5.793 cw(c122.764,-4.463) pad.0@120.939,-4.003 ; pad.0@120.949,-3.953 ccw(c122.937,-4.177) 121.522,-5.592 cw(c122.937,-4.177) pad.0@120.949,-3.953 ; pad.0@120.95,-3.941 ccw(c122.68,-4.085) 121.452,-5.312 cw(c122.68,-4.085) pad.0@120.95,-3.941 ; pad.0@120.951,-3.91 ccw(c122.45,-3.91) 121.39,-4.97 cw(c122.45,-3.91) pad.0@120.951,-3.91 ; pad.0@121.186,-4.065 ccw(c123.269,-4.59) 121.75,-6.11 cw(c123.269,-4.59) pad.0@121.186,-4.065 ; pad.0@121.201,-3.981 ccw(c123.607,-4.253) 121.895,-5.965 cw(c123.607,-4.253) pad.0@121.201,-3.981 ; pad.0@121.203,-3.962 ccw(c123.396,-4.144) 121.84,-5.7 cw(c123.396,-4.144) pad.0@121.203,-3.962 ; 144.222,-10.648 cw(c146.6,-13.026) 146.6,-9.663 ccw(c146.6,-13.026) 144.222,-10.648 ; 144.656,-10.214 cw(c146.6,-12.159) 146.6,-9.409 ccw(c146.6,-12.159) 144.656,-10.214 ; 145.089,-9.781 cw(c146.6,-11.292) 146.6,-9.155 ccw(c146.6,-11.292) 145.089,-9.781 ; 145.309,-9.91 ccw(c145.309,-8.772) 146.392,-9.123 cw(c145.309,-8.772) 145.309,-9.91 ; 145.365,-9.765 cw(c146.297,-10.697) 146.557,-9.405 ccw(c146.297,-10.697) 145.365,-9.765 ; 145.523,-9.347 cw(c146.6,-10.424) 146.6,-8.901 ccw(c146.6,-10.424) 145.523,-9.347 ; 145.547,-9.588 cw(c146.179,-10.219) 146.517,-9.393 ccw(c146.179,-10.219) 145.547,-9.588 ; 145.658,-9.91 ccw(c145.658,-8.885) 146.633,-9.201 cw(c145.658,-8.885) 145.658,-9.91 ; 145.659,-9.77 ccw(c145.659,-9.036) 146.384,-9.155 cw(c145.659,-9.036) 145.659,-9.77 ; 145.7,-9.43 cw(c146.409,-10.138) 146.607,-9.156 ccw(c146.409,-10.138) 145.7,-9.43 ; 145.817,-9.318 cw(c146.335,-9.836) 146.613,-9.158 ccw(c146.335,-9.836) 145.817,-9.318 ; 145.916,-9.53 ccw(c145.916,-9.051) 146.385,-9.146 cw(c145.916,-9.051) 145.916,-9.53 ; 145.934,-9.396 cw(c146.219,-9.681) 146.466,-9.363 ccw(c146.219,-9.681) 145.934,-9.396 ; 145.956,-8.914 cw(c146.6,-9.557) 146.6,-8.647 ccw(c146.6,-9.557) 145.956,-8.914 ; 145.958,-9.77 ccw(c145.958,-9.085) 146.635,-9.196 cw(c145.958,-9.085) 145.958,-9.77 ; 146.008,-9.91 ccw(c146.008,-8.998) 146.875,-9.279 cw(c146.008,-8.998) 146.008,-9.91 ; v1@146.074,-9.056 cw(c146.763,-9.232) 146.763,-8.52 ccw(c146.763,-9.232) v1@146.074,-9.056 ; 146.257,-9.77 ccw(c146.257,-9.134) 146.885,-9.237 cw(c146.257,-9.134) 146.257,-9.77 ; v1@146.311,-9.185 cw(c146.875,-9.194) 146.875,-8.63 ccw(c146.875,-9.194) v1@146.311,-9.185 ; v1@146.32,-9.119 cw(c147.09,-9.315) 147.09,-8.52 ccw(c147.09,-9.315) v1@146.32,-9.119 ; 146.357,-9.91 ccw(c146.357,-9.111) 147.117,-9.357 cw(c146.357,-9.111) 146.357,-9.91 ; v1@146.413,-9.7 ccw(c146.66,-9.027) 147.166,-9.534 cw(c146.66,-9.027) v1@146.413,-9.7 ; v1@146.5,-9.461 ccw(c146.811,-8.617) 147.447,-9.253 cw(c146.811,-8.617) v1@146.5,-9.461 ; v1@146.565,-9.189 cw(c147.134,-9.199) 147.134,-8.63 ccw(c147.134,-9.199) v1@146.565,-9.189 ; v1@146.566,-9.181 cw(c147.417,-9.398) 147.417,-8.52 ccw(c147.417,-9.398) v1@146.566,-9.181 ; v1@146.584,-9.221 ccw(c146.899,-8.617) 147.381,-9.099 cw(c146.899,-8.617) v1@146.584,-9.221 ; v1@146.588,-9.223 ccw(c146.962,-8.206) 147.728,-8.972 cw(c146.962,-8.206) v1@146.588,-9.223 ; v1@146.676,-8.984 ccw(c147.113,-7.795) 148.009,-8.691 cw(c147.113,-7.795) v1@146.676,-8.984 ; v1@146.701,-8.996 ccw(c147.067,-8.296) 147.625,-8.855 cw(c147.067,-8.296) v1@146.701,-8.996 ; v1@146.812,-9.244 cw(c147.743,-9.481) 147.743,-8.52 ccw(c147.743,-9.481) v1@146.812,-9.244 ; v1@146.819,-9.195 cw(c147.161,-9.202) 147.161,-8.86 ccw(c147.161,-9.202) v1@146.819,-9.195 ; v1@146.819,-9.194 cw(c147.392,-9.203) 147.392,-8.63 ccw(c147.392,-9.203) v1@146.819,-9.194 ; v1@147.073,-9.198 cw(c147.65,-9.207) 147.65,-8.63 ccw(c147.65,-9.207) v1@147.073,-9.198 ; 157.672,-7.97 ccw(c157.672,-4.882) 159.856,-7.066 cw(c157.672,-4.882) 157.672,-7.97 ; 158.285,-7.97 ccw(c158.285,-5.495) 160.035,-7.245 cw(c158.285,-5.495) 158.285,-7.97 ; 158.898,-7.97 ccw(c158.898,-6.108) 160.215,-7.425 cw(c158.898,-6.108) 158.898,-7.97 ; 159.512,-7.97 ccw(c159.512,-6.722) 160.394,-7.604 cw(c159.512,-6.722) 159.512,-7.97 ; v1@159.986,-7.604 ccw(c160.868,-6.722) 160.868,-7.97 cw(c160.868,-6.722) v1@159.986,-7.604 ; v1@160.165,-7.425 ccw(c161.482,-6.108) 161.482,-7.97 cw(c161.482,-6.108) v1@160.165,-7.425 ; v1@160.345,-7.245 ccw(c162.095,-5.495) 162.095,-7.97 cw(c162.095,-5.495) v1@160.345,-7.245 ; v1@160.524,-7.066 ccw(c162.708,-4.882) 162.708,-7.97 cw(c162.708,-4.882) v1@160.524,-7.066
  Carbon Ink Layer w1.2: KP2.2@12.63,1.768 v1(15.96,1.77) ; v1@28.68,5.12 31.233,2.567 31.233,-1.737 30.51,-2.46 v1(30.51,-2.43) ; KP56.2@50.965,0.028 KP56.2@51.033,-0.04 v1@51.033,-7.09 ; 51.033,-6.353 51.04,-6.36 51.04,-6.35 ; KP53.1@81.326,0.11 v1(82.56,-6.48) ; KP8.1@105.069,0.925 104.85,0.706 104.85,-7.18 v1(106.02,-8.35) ; KP43.2@134.1,0.22 134.1,2.08 v1@136.03,4.01 ; 134.1,0.57 134.12,0.55 ; KP43.2@134.273,0.01 KP43.2@134.333,-0.05 ; v1@136.406,4.064 136.96,3.51 ; v1@143.251,-2.507 145.173,-8.107 146.441,-8.726 v1(146.6,-9.19) ; KP37.2@159.41,-2.917 160.19,-3.697 v1(160.19,-7.4) ; v1(146.6,-9.19) ccw(c145.481,-9.574) 146.001,-8.511 cw(c145.481,-9.574) v1(146.6,-9.19)
  other v1: 51.04,-7.08 28.67,5.13
PC3_2: J1.4 pad.0@139.82,21.6 | length 166.2
  Top Layer w0.254: 139.21,20.16 139.87,19.5 ; pad.0@139.21,21.74 139.21,20 139.71,19.5 144.81,19.5 145.81,20.5 145.81,21.63 146.74,22.56 160.4,22.56 162.61,20.35 164.07,20.35 166.28,22.56 177.61,22.56 177.995,22.945 187.124,22.945 ; 139.443,20.033 cw(c139.917,20.379) 139.57,20.853 ; 139.47,20.18 pad.0@139.47,21.42 ; pad.0@139.59,21.5 139.59,20 140.09,19.5 ; 139.77,20.01 139.77,20.65 ; pad.0@139.82,21.6 139.82,20.25 ; 139.885,19.705 pad.0@139.885,21.394 ; 140.13,19.62 pad.0@140.13,21.44 ; 140.27,19.5 pad.0@140.27,21.38 ; 140.43,20 140.73,19.7 144.95,19.7 ; pad.0@140.43,21.75 140.43,19.78 140.71,19.5 ; 160.82,22.14 162.082,20.878 ; 187.124,22.936 cw(c187.124,20.672) 188.724,22.273 190.399,20.598 cw(c188.603,18.802) 191.143,18.802 191.143,18.475 ccw(c193.683,18.475) 191.886,16.679 194.272,14.293 ccw(c196.068,16.089) 196.068,13.549 196.55,13.549 cw(c196.55,11.535) 197.974,12.959 200.959,9.975 cw(c199.162,8.179) 201.702,8.179 201.702,6.103 cw(c199.162,6.103) 200.959,4.307 199.723,3.072 ccw(c200.17,2.625) 199.538,2.625 199.538,2.542 ccw(c200.674,2.542) 199.871,1.739 ; J1.4@199.996,1.348 ccw(c199.553,1.421) 199.871,1.739 ; J1.4@200.262,1.614 cw(c200.189,2.057) 199.871,1.739 ; J1.4@200.315,1.295 199.871,1.739 ; pad.0@139.371,21.151 cw(c138.13,19.91) 139.885,19.91 ccw(c138.13,19.91) pad.0@139.371,21.151 ; pad.0@139.371,21.151 cw(c138.842,20.622) 139.59,20.622 ccw(c138.842,20.622) pad.0@139.371,21.151 ; pad.0@139.371,21.151 cw(c139.132,20.912) 139.47,20.912 ccw(c139.132,20.912) pad.0@139.371,21.151 ; 139.82,20.25 cw(c140.937,20.25) 140.225,21.111 ccw(c140.937,20.25) 139.82,20.25 ; 139.82,20.25 ccw(c138.703,20.25) 139.415,21.111 cw(c138.703,20.25) 139.82,20.25 ; 139.82,20.79 cw(c140.49,20.79) 140.063,21.307 ccw(c140.49,20.79) 139.82,20.79 ; 139.82,20.79 ccw(c139.15,20.79) 139.577,21.307 cw(c139.15,20.79) 139.82,20.79 ; pad.0@140.269,21.151 ccw(c140.605,20.815) 140.13,20.815 cw(c140.605,20.815) pad.0@140.269,21.151 ; pad.0@140.269,21.151 ccw(c141.196,20.224) 139.885,20.224 cw(c141.196,20.224) pad.0@140.269,21.151 ; 139.21,20.237 cw(c140.262,20.237) 139.937,21.238 ccw(c140.262,20.237) 139.21,20.237 ; 139.21,20.586 cw(c140.149,20.586) 139.859,21.479 ccw(c140.149,20.586) 139.21,20.586 ; 139.21,20.936 cw(c140.035,20.936) 139.781,21.721 ccw(c140.035,20.936) 139.21,20.936 ; pad.0@139.416,21.11 cw(c138.168,19.596) 140.13,19.596 ccw(c138.168,19.596) pad.0@139.416,21.11 ; 139.47,20.138 cw(c140.413,20.138) 140.059,21.012 ccw(c140.413,20.138) 139.47,20.138 ; 139.47,20.515 cw(c140.26,20.515) 139.963,21.247 ccw(c140.26,20.515) 139.47,20.515 ; 139.47,20.892 cw(c140.107,20.892) 139.868,21.482 ccw(c140.107,20.892) 139.47,20.892 ; pad.0@139.551,21.331 cw(c138.743,20.523) 139.885,20.523 ccw(c138.743,20.523) pad.0@139.551,21.331 ; pad.0@139.561,21.02 cw(c138.963,19.681) 140.43,19.681 ccw(c138.963,19.681) pad.0@139.561,21.02 ; pad.0@139.578,21.306 cw(c138.612,20.135) 140.13,20.135 ccw(c138.612,20.135) pad.0@139.578,21.306 ; 139.59,19.984 cw(c140.898,19.984) 140.172,21.072 ccw(c140.898,19.984) 139.59,19.984 ; 139.59,20.458 cw(c140.581,20.458) 140.031,21.283 ccw(c140.581,20.458) 139.59,20.458 ; pad.0@139.594,21.293 cw(c138.608,19.955) 140.27,19.955 ccw(c138.608,19.955) pad.0@139.594,21.293 ; pad.0@139.665,21.252 cw(c139.138,20.072) 140.43,20.072 ccw(c139.138,20.072) pad.0@139.665,21.252 ; pad.0@139.739,21.502 cw(c139.056,20.673) 140.13,20.673 ccw(c139.056,20.673) pad.0@139.739,21.502 ; pad.0@139.745,21.498 cw(c138.978,20.458) 140.27,20.458 ccw(c138.978,20.458) pad.0@139.745,21.498 ; pad.0@139.768,21.484 cw(c139.313,20.464) 140.43,20.464 ccw(c139.313,20.464) pad.0@139.768,21.484 ; pad.0@139.872,21.716 cw(c139.487,20.855) 140.43,20.855 ccw(c139.487,20.855) pad.0@139.872,21.716 ; 139.885,20.837 cw(c140.583,20.837) 140.089,21.331 ccw(c140.583,20.837) 139.885,20.837 ; pad.0@139.895,21.702 cw(c139.349,20.961) 140.27,20.961 ccw(c139.349,20.961) pad.0@139.895,21.702
PC4: pad.5 U1.35 | length 107.3
  Top Layer w0.254: pad.5@108.19,-9.1 110.19,-9.1 ; pad.5@108.21,-8.36 110.93,-8.36 ; pad.5@108.5,-9.57 109.72,-9.57 111.09,-8.2 117.86,-8.2 119.38,-6.68 121.03,-6.68 121.65,-7.3 121.65,-10.34 124.972,-13.662 136.568,-13.662 137.99,-12.24 143.45,-12.24 145.21,-10.48 147.42,-10.48 148.9,-9 151.87,-9 152.29,-8.58 168.13,-8.58 169.315,-7.395 169.315,-7.013 cw(c171.855,-7.013) 170.058,-5.217 173.69,-1.585 ; pad.5@108.519,-8.721 ccw(c109.435,-7.805) 109.435,-9.1 ; pad.5@108.555,-8.761 ccw(c109.232,-8.254) 109.232,-9.1 ; pad.5@108.699,-8.541 ccw(c110.049,-7.191) 110.049,-9.1 ; 108.95,-9.57 109.268,-9.252 ; 109.04,-8.58 109.49,-8.58 ; 109.18,-8.75 109.63,-8.75 ; 109.208,-8.609 108.758,-8.609 ccw(c109.74,-7.873) 109.74,-9.1 ; 109.25,-9.43 109.568,-9.112 ; 109.34,-8.92 109.79,-8.92 ; 109.43,-9.45 109.748,-9.132 ; 109.43,-8.36 110.14,-9.07 ; 109.58,-8.71 110.39,-8.71 ; 109.63,-9.47 109.948,-9.152 ; 109.75,-8.52 110.56,-8.52 ; 109.88,-8.85 110.33,-8.85 ; 110.08,-8.69 110.53,-8.69 ; 173.688,-1.587 174.514,-0.761 ; 174.503,-0.777 174.777,-0.503 cw(c175.95,-1.677) 175.95,-0.017 179.495,-0.017 cw(c179.495,-2.557) 181.291,-0.761 183.595,-3.065 cw(c183.333,-3.327) 183.703,-3.327 U1.35@183.703,-3.75 ; pad.5@108.699,-9.439 cw(c109.517,-10.257) 109.517,-9.1 ccw(c109.517,-10.257) pad.5@108.699,-9.439
PC4_1: 
PC4_2: 
PC4_3: J1.7 pad.7 | length 125.4
  Top Layer w0.254: pad.7@127.73,19.52 129.95,19.52 ; pad.7@127.83,20.21 137.84,20.21 139.23,18.82 151.32,18.82 ; pad.7@127.84,19.73 130.06,19.73 ; pad.7@127.96,19.85 130.18,19.85 ; pad.7@127.97,19.31 129.75,19.31 130.68,20.24 ; pad.7@128.03,20.54 130.25,20.54 ; pad.7@128.05,20.66 130.27,20.66 130.69,20.24 ; pad.7@128.12,20.4 130.34,20.4 ; pad.7@128.14,19.84 cw(c129.033,18.947) 129.033,20.21 ; pad.7@128.2,20.08 130.42,20.08 ; pad.7@128.319,19.661 cw(c129.646,18.334) 129.646,20.21 ; pad.7@128.499,19.481 cw(c130.259,17.721) 130.259,20.21 ; pad.7@128.499,20.379 ccw(c128.907,20.787) 128.907,20.21 ; 151.42,18.82 152.82,20.22 159.94,20.22 161.64,18.52 165.4,18.52 167.1,20.22 176.16,20.22 177.36,19.02 187.143,19.02 188.311,17.851 cw(c187.62,17.16) 188.597,17.16 ; 188.614,17.254 ccw(c189.853,17.254) 188.977,16.378 193.34,12.014 ccw(c195.137,13.81) 195.137,11.27 195.729,11.27 cw(c195.729,9.523) 196.965,10.759 198.246,9.477 cw(c196.45,7.681) 198.99,7.681 198.99,6.732 cw(c196.45,6.732) 198.246,4.936 197.992,4.682 ccw(c199.789,2.886) 197.249,2.886 197.249,-0.286 ccw(c199.789,-0.286) 197.992,-2.082 199.508,-3.598 ccw(c200.039,-3.066) 199.707,-3.74 ccw(c200.039,-3.066) 199.957,-3.813 ccw(c200.039,-3.066) 200.039,-3.818 201.603,-3.818 ; 201.507,-3.818 ccw(c201.408,-2.816) 202.12,-3.528 ccw(c201.323,-2.731) 202.45,-2.731 202.45,-2.542 ccw(c201.635,-2.542) 202.211,-1.966 201.652,-1.407 cw(c201.814,-1.245) J1.7@201.585,-1.245 ; J1.7@201.908,-1.245 ccw(c202.917,-1.245) 202.203,-1.958 ; J1.7@201.585,-1.568 cw(c201.585,-2.119) 201.975,-1.729 ; J1.7@201.585,-1.568 cw(c201.585,-2.119) 201.975,-1.729 ; J1.7@201.585,-1.568 cw(c201.585,-2.119) 201.975,-1.729 ; J1.7@201.908,-1.259 ccw(c202.785,-1.298) 202.164,-1.919 cw(c202.785,-1.298) J1.7@201.908,-1.259
PC5: KP10.2 KP33.1 KP39.1 KP51.2 KP60.2 KP64.2 U1.11 | length 306.6
  Top Layer w0.254: v1(27.737,14.573) 58.973,14.573 62.53,18.13 70.85,18.13 75.35,13.63 81.15,13.63 83.16,15.64 ; 83.37,15.64 ccw(c83.37,17.491) v1@84.886,16.429 ; 83.702,15.64 ccw(c83.702,17.465) v1@85.105,16.297 ; 83.858,15.64 ccw(c83.858,17.149) v1@85.094,16.283 ; 84.244,15.64 ccw(c84.244,17.014) v1@85.3,16.135 ; 84.346,15.64 ccw(c84.346,16.806) v1@85.302,16.137 ; 84.786,15.64 ccw(c84.786,16.562) v1@85.495,15.972 ; 84.835,15.64 ccw(c84.835,16.464) v1@85.51,15.991 ; v1@84.909,16.46 cw(c83.16,17.917) 83.16,15.64 ; 107.632,14.58 ccw(c107.632,16.363) v1@108.895,15.105 ; 108.243,14.58 ccw(c108.243,15.754) v1@109.075,14.925 ; v1@108.715,15.284 cw(c107.02,16.972) 107.02,14.58 ; v1@109.01,14.91 v1(109.05,14.95) v1@109.05,14.94 ; v1@109.025,14.925 ccw(c109.859,15.759) 109.859,14.58 ; v1@109.205,15.105 ccw(c110.472,16.372) 110.472,14.58 ; v1@109.384,15.284 ccw(c111.085,16.985) 111.085,14.58 ; 130.769,18.81 cw(c130.769,17.401) v1@131.766,18.397 ; 131.147,18.81 ccw(c131.147,19.685) v1@131.766,19.066 ; 131.383,18.81 cw(c131.383,18.015) v1@131.945,18.577 ; v1@132.255,18.577 cw(c132.817,18.015) 132.817,18.81 ; v1@132.434,18.397 cw(c133.431,17.401) 133.431,18.81 ; v1@132.434,19.066 ccw(c133.053,19.685) 133.053,18.81 ; v1(171.5,18.7) 171.5,19.52 ; 171.6,19.62 171.5,19.52 ; 175.45,19.62 167.44,19.62 165.78,17.96 161.33,17.96 159.67,19.62 153,19.62 151.6,18.22 137.19,18.22 136.6,18.81 129.81,18.81 128.99,17.99 123.4,17.99 119.99,14.58 107.02,14.58 ; 175.53,19.62 176.74,18.41 186.89,18.41 187.665,17.635 187.665,16.845 ccw(c188.739,16.845) 187.98,16.085 195.597,8.468 cw(c193.801,6.672) 196.341,6.672 196.341,4.665 ; U1.11@188.203,-10.6 188.203,-10.926 ccw(c188.561,-10.926) 188.308,-11.179 188.516,-11.388 188.92,-11.388 190.099,-12.567 cw(c189.783,-12.882) 190.23,-12.882 ccw(c190.646,-12.882) 190.352,-13.177 190.681,-13.506 ccw(c192.477,-11.71) 192.477,-14.25 194.625,-14.25 ; 194.618,-14.255 196.291,-14.255 ccw(c196.291,-13.214) 197.028,-13.95 ccw(c196.271,-13.193) 197.341,-13.193 197.341,-3.862 ; 196.341,4.655 196.341,-0.977 ccw(c198.311,-0.977) 196.918,-2.37 cw(c195.898,-3.39) 197.34,-3.39 197.34,-3.858 ; 28.879,14.573 cw(c28.879,15.715) 28.072,14.907 ccw(c28.879,15.715) 28.879,14.573 ; 28.879,14.573 ccw(c28.879,13.431) 28.072,14.238 cw(c28.879,13.431) 28.879,14.573 ; 44.508,14.573 cw(c44.508,13.431) 45.316,14.238 ccw(c44.508,13.431) 44.508,14.573 ; 44.508,14.573 ccw(c44.508,15.715) 45.316,14.907 cw(c44.508,15.715) 44.508,14.573 ; 46.792,14.573 cw(c46.792,15.715) 45.984,14.907 ccw(c46.792,15.715) 46.792,14.573 ; 46.792,14.573 ccw(c46.792,13.431) 45.984,14.238 cw(c46.792,13.431) 46.792,14.573 ; 83.16,15.64 94.94,15.64 99.04,11.54 103.98,11.54 107.02,14.58 ; 171.5,19.52 cw(c171.026,19.52) 171.263,19.109 ccw(c171.026,19.52) 171.5,19.52 ; 171.5,19.52 ccw(c171.974,19.52) 171.737,19.109 cw(c171.974,19.52) 171.5,19.52 ; v1@85.069,15.953 ccw(c85.824,16.708) 85.824,15.64 cw(c85.824,16.708) v1@85.069,15.953 ; v1@85.248,16.132 ccw(c86.437,17.321) 86.437,15.64 cw(c86.437,17.321) v1@85.248,16.132 ; v1@85.428,16.312 ccw(c87.05,17.934) 87.05,15.64 cw(c87.05,17.934) v1@85.428,16.312 ; v1@85.607,16.492 ccw(c87.663,18.547) 87.663,15.64 cw(c87.663,18.547) v1@85.607,16.492
  Carbon Ink Layer w1.2: KP64.2@23.2,14.573 v1(27.737,14.573) ; KP60.2@41.923,6.46 41.923,9.243 45.616,12.936 v1@45.616,14.606 ; KP51.2@85.273,7.38 v1(85.273,16.157) ; v1@109.05,14.94 109.05,10.66 112.386,7.324 KP10.2@112.977,7.324 ; KP39.1@132.1,15.96 v1(132.1,18.732) ; 132.284,15.41 KP39.1@132.284,15.93 ; KP33.1@171.226,16.1 v1(171.5,18.7)
  other v1: 45.65,14.573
